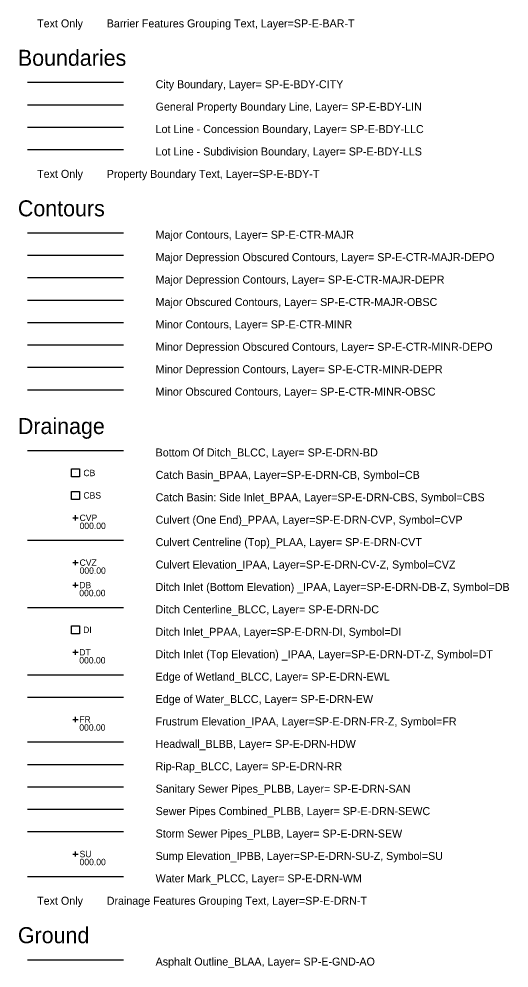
# Model space of a CAD drawing. Extents: x 500528 to 502626, y 4210261 to 4212624.
# Drawn here: x 500883.9 to 501036.9, y 4212030 to 4212326.4 of the extents above; entities that cross this region are included whole.
import ezdxf

# ---------------------------------------------------------------- set-up
doc = ezdxf.new("R2010")
doc.units = 0
for name, color, linetype in [('Default', 7, 'Continuous'), ('SP-E-BAR-T', 7, 'Continuous'), ('SP-E-BDY-CITY', 7, 'Continuous'), ('SP-E-BDY-LIN', 7, 'Continuous'), ('SP-E-BDY-LLC', 7, 'Continuous'), ('SP-E-BDY-LLS', 7, 'Continuous'), ('SP-E-BDY-T', 7, 'Continuous'), ('SP-E-CTR-MAJR', 7, 'Continuous'), ('SP-E-CTR-MAJR-DEPO', 7, 'Continuous'), ('SP-E-CTR-MAJR-DEPR', 7, 'Continuous'), ('SP-E-CTR-MAJR-OBSC', 7, 'Continuous'), ('SP-E-CTR-MINR', 7, 'Continuous'), ('SP-E-CTR-MINR-DEPO', 7, 'Continuous'), ('SP-E-CTR-MINR-DEPR', 7, 'Continuous'), ('SP-E-CTR-MINR-OBSC', 7, 'Continuous'), ('SP-E-DRN-BD', 7, 'Continuous'), ('SP-E-DRN-CB', 7, 'Continuous'), ('SP-E-DRN-CBS', 7, 'Continuous'), ('SP-E-DRN-CV-Z', 7, 'Continuous'), ('SP-E-DRN-CVP', 7, 'Continuous'), ('SP-E-DRN-CVT', 7, 'Continuous'), ('SP-E-DRN-DB-Z', 7, 'Continuous'), ('SP-E-DRN-DC', 7, 'Continuous'), ('SP-E-DRN-DI', 7, 'Continuous'), ('SP-E-DRN-DT-Z', 7, 'Continuous'), ('SP-E-DRN-EW', 7, 'Continuous'), ('SP-E-DRN-EWL', 7, 'Continuous'), ('SP-E-DRN-FR-Z', 7, 'Continuous'), ('SP-E-DRN-HDW', 7, 'Continuous'), ('SP-E-DRN-RR', 7, 'Continuous'), ('SP-E-DRN-SAN', 7, 'Continuous'), ('SP-E-DRN-SEW', 7, 'Continuous'), ('SP-E-DRN-SEWC', 7, 'Continuous'), ('SP-E-DRN-SU-Z', 7, 'Continuous'), ('SP-E-DRN-T', 7, 'Continuous'), ('SP-E-DRN-WM', 7, 'Continuous'), ('SP-E-GND-AO', 7, 'Continuous')]:
    doc.layers.add(name, color=color, linetype=linetype)

# ---------------------------------------------------------------- blocks, each defined once
blk = doc.blocks.new('POINT_DISPLAY')
at = {"layer": 'Default'}
blk.add_line((0, 0), (0, 0), dxfattribs=at)
blk = doc.blocks.new('CB')
at = {"layer": 'SP-E-DRN-T'}
blk.add_lwpolyline([(-0.125, 0.125), (0.125, 0.125), (0.125, -0.125), (-0.125, -0.125), (-0.125, 0.125)], dxfattribs=at)
at = {"layer": 'SP-E-DRN-CB'}
blk.add_blockref('POINT_DISPLAY', (0, 0), dxfattribs=at)
at = {"layer": 'SP-E-DRN-T'}
blk.add_text('CB', height=0.2, dxfattribs=at).set_placement((0.246, -0.1))
blk = doc.blocks.new('CBS')
at = {"layer": 'SP-E-DRN-T'}
blk.add_lwpolyline([(-0.125, 0.125), (0.125, 0.125), (0.125, -0.125), (-0.125, -0.125), (-0.125, 0.125)], dxfattribs=at)
at = {"layer": 'SP-E-DRN-CBS'}
blk.add_blockref('POINT_DISPLAY', (0, 0), dxfattribs=at)
at = {"layer": 'SP-E-DRN-T'}
blk.add_text('CBS', height=0.2, dxfattribs=at).set_placement((0.246, -0.1))
blk = doc.blocks.new('CVP')
at = {"layer": 'SP-E-DRN-CVP'}
for points in [[(-0.08, 0), (0.08, 0)], [(0, -0.08), (0, 0.08)]]:
    blk.add_lwpolyline(points, dxfattribs=at)
at = {"layer": 'SP-E-DRN-T'}
for s, p in [('CVP', (0.126, -0.1)), ('000.00', (0.126, -0.35))]:
    blk.add_text(s, height=0.2, dxfattribs=at).set_placement(p)
blk = doc.blocks.new('CVZ')
at = {"layer": 'SP-E-DRN-CV-Z'}
for points in [[(-0.08, 0), (0.08, 0)], [(0, -0.08), (0, 0.08)]]:
    blk.add_lwpolyline(points, dxfattribs=at)
at = {"layer": 'SP-E-DRN-T'}
for s, p in [('CVZ', (0.126, -0.1)), ('000.00', (0.126, -0.35))]:
    blk.add_text(s, height=0.2, dxfattribs=at).set_placement(p)
blk = doc.blocks.new('DB')
at = {"layer": 'SP-E-DRN-DB-Z'}
for points in [[(-0.08, 0), (0.08, 0)], [(0, -0.08), (0, 0.08)]]:
    blk.add_lwpolyline(points, dxfattribs=at)
at = {"layer": 'SP-E-DRN-T'}
for s, p in [('DB', (0.117, -0.1)), ('000.00', (0.117, -0.35))]:
    blk.add_text(s, height=0.2, dxfattribs=at).set_placement(p)
blk = doc.blocks.new('DI')
at = {"layer": 'SP-E-DRN-DI'}
for points in [[(-0.125, 0.125), (0.125, 0.125), (0.125, -0.125), (-0.125, -0.125), (-0.125, 0.125)], [(0, 0), (0, 0)]]:
    blk.add_lwpolyline(points, dxfattribs=at)
at = {"layer": 'SP-E-DRN-T'}
blk.add_text('DI', height=0.2, dxfattribs=at).set_placement((0.237, -0.1))
blk = doc.blocks.new('DT')
at = {"layer": 'SP-E-DRN-DT-Z'}
for points in [[(-0.08, 0), (0.08, 0)], [(0, -0.08), (0, 0.08)]]:
    blk.add_lwpolyline(points, dxfattribs=at)
at = {"layer": 'SP-E-DRN-T'}
for s, p in [('DT', (0.117, -0.1)), ('000.00', (0.117, -0.35))]:
    blk.add_text(s, height=0.2, dxfattribs=at).set_placement(p)
blk = doc.blocks.new('FR')
at = {"layer": 'SP-E-DRN-FR-Z'}
for points in [[(-0.08, 0), (0.08, 0)], [(0, -0.08), (0, 0.08)]]:
    blk.add_lwpolyline(points, dxfattribs=at)
at = {"layer": 'SP-E-DRN-T'}
for s, p in [('FR', (0.117, -0.1)), ('000.00', (0.117, -0.35))]:
    blk.add_text(s, height=0.2, dxfattribs=at).set_placement(p)
blk = doc.blocks.new('SU')
at = {"layer": 'SP-E-DRN-SU-Z'}
for points in [[(-0.08, 0), (0.08, 0)], [(0, -0.08), (0, 0.08)]]:
    blk.add_lwpolyline(points, dxfattribs=at)
at = {"layer": 'SP-E-DRN-T'}
for s, p in [('SU', (0.126, -0.1)), ('000.00', (0.126, -0.35))]:
    blk.add_text(s, height=0.2, dxfattribs=at).set_placement(p)

msp = doc.modelspace()

# ---------------------------------------------------------------- linework, layer by layer
at = {"layer": 'SP-E-BDY-CITY'}
msp.add_line((500886.55, 4212306.59), (500916.55, 4212306.59), dxfattribs=at)
at = {"layer": 'SP-E-BDY-LIN'}
msp.add_line((500886.55, 4212299.59), (500916.55, 4212299.59), dxfattribs=at)
at = {"layer": 'SP-E-BDY-LLC'}
msp.add_line((500886.55, 4212292.59), (500916.55, 4212292.59), dxfattribs=at)
at = {"layer": 'SP-E-BDY-LLS'}
msp.add_line((500886.55, 4212285.59), (500916.55, 4212285.59), dxfattribs=at)
at = {"layer": 'SP-E-CTR-MAJR'}
msp.add_line((500886.55, 4212259.59), (500916.55, 4212259.59), dxfattribs=at)
at = {"layer": 'SP-E-CTR-MAJR-DEPO'}
msp.add_line((500886.55, 4212252.59), (500916.55, 4212252.59), dxfattribs=at)
at = {"layer": 'SP-E-CTR-MAJR-DEPR'}
msp.add_line((500886.55, 4212245.59), (500916.55, 4212245.59), dxfattribs=at)
at = {"layer": 'SP-E-CTR-MAJR-OBSC'}
msp.add_line((500886.55, 4212238.59), (500916.55, 4212238.59), dxfattribs=at)
at = {"layer": 'SP-E-CTR-MINR'}
msp.add_line((500886.55, 4212231.59), (500916.55, 4212231.59), dxfattribs=at)
at = {"layer": 'SP-E-CTR-MINR-DEPO'}
msp.add_line((500886.55, 4212224.59), (500916.55, 4212224.59), dxfattribs=at)
at = {"layer": 'SP-E-CTR-MINR-DEPR'}
msp.add_line((500886.55, 4212217.59), (500916.55, 4212217.59), dxfattribs=at)
at = {"layer": 'SP-E-CTR-MINR-OBSC'}
msp.add_line((500886.55, 4212210.59), (500916.55, 4212210.59), dxfattribs=at)
at = {"layer": 'SP-E-DRN-BD'}
msp.add_line((500886.55, 4212191.59), (500916.55, 4212191.59), dxfattribs=at)
at = {"layer": 'SP-E-DRN-CVT'}
msp.add_line((500886.55, 4212163.59), (500916.55, 4212163.59), dxfattribs=at)
at = {"layer": 'SP-E-DRN-DC'}
msp.add_line((500886.55, 4212142.59), (500916.55, 4212142.59), dxfattribs=at)
at = {"layer": 'SP-E-DRN-EW'}
msp.add_line((500886.55, 4212114.59), (500916.55, 4212114.59), dxfattribs=at)
at = {"layer": 'SP-E-DRN-EWL'}
msp.add_line((500886.55, 4212121.59), (500916.55, 4212121.59), dxfattribs=at)
at = {"layer": 'SP-E-DRN-HDW'}
msp.add_line((500886.55, 4212100.59), (500916.55, 4212100.59), dxfattribs=at)
at = {"layer": 'SP-E-DRN-RR'}
msp.add_line((500886.55, 4212093.59), (500916.55, 4212093.59), dxfattribs=at)
at = {"layer": 'SP-E-DRN-SAN'}
msp.add_line((500886.55, 4212086.59), (500916.55, 4212086.59), dxfattribs=at)
at = {"layer": 'SP-E-DRN-SEW'}
msp.add_line((500886.55, 4212072.59), (500916.55, 4212072.59), dxfattribs=at)
at = {"layer": 'SP-E-DRN-SEWC'}
msp.add_line((500886.55, 4212079.59), (500916.55, 4212079.59), dxfattribs=at)
at = {"layer": 'SP-E-DRN-WM'}
msp.add_line((500886.55, 4212058.59), (500916.55, 4212058.59), dxfattribs=at)
at = {"layer": 'SP-E-GND-AO'}
msp.add_line((500886.55, 4212032.59), (500916.55, 4212032.59), dxfattribs=at)

# ---------------------------------------------------------------- block references
at = {"layer": 'SP-E-DRN-CB', "xscale": 10, "yscale": 10}
msp.add_blockref('CB', (500901.55, 4212184.59), dxfattribs=at)
at = {"layer": 'SP-E-DRN-CBS', "xscale": 10, "yscale": 10}
msp.add_blockref('CBS', (500901.55, 4212177.59), dxfattribs=at)
at = {"layer": 'SP-E-DRN-CV-Z', "xscale": 10, "yscale": 10}
msp.add_blockref('CVZ', (500901.55, 4212156.59), dxfattribs=at)
at = {"layer": 'SP-E-DRN-CVP', "xscale": 10, "yscale": 10}
msp.add_blockref('CVP', (500901.55, 4212170.59), dxfattribs=at)
at = {"layer": 'SP-E-DRN-DB-Z', "xscale": 10, "yscale": 10}
msp.add_blockref('DB', (500901.55, 4212149.59), dxfattribs=at)
at = {"layer": 'SP-E-DRN-DI', "xscale": 10, "yscale": 10}
msp.add_blockref('DI', (500901.55, 4212135.59), dxfattribs=at)
at = {"layer": 'SP-E-DRN-DT-Z', "xscale": 10, "yscale": 10}
msp.add_blockref('DT', (500901.55, 4212128.59), dxfattribs=at)
at = {"layer": 'SP-E-DRN-FR-Z', "xscale": 10, "yscale": 10}
msp.add_blockref('FR', (500901.55, 4212107.59), dxfattribs=at)
at = {"layer": 'SP-E-DRN-SU-Z', "xscale": 10, "yscale": 10}
msp.add_blockref('SU', (500901.55, 4212065.59), dxfattribs=at)

# ---------------------------------------------------------------- texts
at = {"layer": 'Default'}
for s, p in [('Boundaries ', (500883.55, 4212311.74)), ('Contours ', (500883.55, 4212264.74)), ('Drainage ', (500883.55, 4212196.74)), ('Ground ', (500883.55, 4212037.74))]:
    msp.add_text(s, height=5, dxfattribs=at).set_placement(p)
at = {"layer": 'SP-E-BAR-T'}
msp.add_text('Text Only        Barrier Features Grouping Text, Layer=SP-E-BAR-T', height=2.5, dxfattribs=at).set_placement((500889.55, 4212323.74))
at = {"layer": 'SP-E-BDY-CITY'}
msp.add_text('City Boundary, Layer= SP-E-BDY-CITY ', height=2.5, dxfattribs=at).set_placement((500926.55, 4212304.74))
at = {"layer": 'SP-E-BDY-LIN'}
msp.add_text('General Property Boundary Line, Layer= SP-E-BDY-LIN ', height=2.5, dxfattribs=at).set_placement((500926.55, 4212297.74))
at = {"layer": 'SP-E-BDY-LLC'}
msp.add_text('Lot Line - Concession Boundary, Layer= SP-E-BDY-LLC ', height=2.5, dxfattribs=at).set_placement((500926.55, 4212290.74))
at = {"layer": 'SP-E-BDY-LLS'}
msp.add_text('Lot Line - Subdivision Boundary, Layer= SP-E-BDY-LLS ', height=2.5, dxfattribs=at).set_placement((500926.55, 4212283.74))
at = {"layer": 'SP-E-BDY-T'}
msp.add_text('Text Only        Property Boundary Text, Layer=SP-E-BDY-T', height=2.5, dxfattribs=at).set_placement((500889.55, 4212276.74))
at = {"layer": 'SP-E-CTR-MAJR'}
msp.add_text('Major Contours, Layer= SP-E-CTR-MAJR ', height=2.5, dxfattribs=at).set_placement((500926.55, 4212257.74))
at = {"layer": 'SP-E-CTR-MAJR-DEPO'}
msp.add_text('Major Depression Obscured Contours, Layer= SP-E-CTR-MAJR-DEPO ', height=2.5, dxfattribs=at).set_placement((500926.55, 4212250.74))
at = {"layer": 'SP-E-CTR-MAJR-DEPR'}
msp.add_text('Major Depression Contours, Layer= SP-E-CTR-MAJR-DEPR ', height=2.5, dxfattribs=at).set_placement((500926.55, 4212243.74))
at = {"layer": 'SP-E-CTR-MAJR-OBSC'}
msp.add_text('Major Obscured Contours, Layer= SP-E-CTR-MAJR-OBSC ', height=2.5, dxfattribs=at).set_placement((500926.55, 4212236.74))
at = {"layer": 'SP-E-CTR-MINR'}
msp.add_text('Minor Contours, Layer= SP-E-CTR-MINR ', height=2.5, dxfattribs=at).set_placement((500926.55, 4212229.74))
at = {"layer": 'SP-E-CTR-MINR-DEPO'}
msp.add_text('Minor Depression Obscured Contours, Layer= SP-E-CTR-MINR-DEPO ', height=2.5, dxfattribs=at).set_placement((500926.55, 4212222.74))
at = {"layer": 'SP-E-CTR-MINR-DEPR'}
msp.add_text('Minor Depression Contours, Layer= SP-E-CTR-MINR-DEPR ', height=2.5, dxfattribs=at).set_placement((500926.55, 4212215.74))
at = {"layer": 'SP-E-CTR-MINR-OBSC'}
msp.add_text('Minor Obscured Contours, Layer= SP-E-CTR-MINR-OBSC ', height=2.5, dxfattribs=at).set_placement((500926.55, 4212208.74))
at = {"layer": 'SP-E-DRN-BD'}
msp.add_text('Bottom Of Ditch_BLCC, Layer= SP-E-DRN-BD ', height=2.5, dxfattribs=at).set_placement((500926.55, 4212189.74))
at = {"layer": 'SP-E-DRN-CB'}
msp.add_text('Catch Basin_BPAA, Layer=SP-E-DRN-CB, Symbol=CB ', height=2.5, dxfattribs=at).set_placement((500926.55, 4212182.74))
at = {"layer": 'SP-E-DRN-CBS'}
msp.add_text('Catch Basin: Side Inlet_BPAA, Layer=SP-E-DRN-CBS, Symbol=CBS ', height=2.5, dxfattribs=at).set_placement((500926.55, 4212175.74))
at = {"layer": 'SP-E-DRN-CV-Z'}
msp.add_text('Culvert Elevation_IPAA, Layer=SP-E-DRN-CV-Z, Symbol=CVZ ', height=2.5, dxfattribs=at).set_placement((500926.55, 4212154.74))
at = {"layer": 'SP-E-DRN-CVP'}
msp.add_text('Culvert (One End)_PPAA, Layer=SP-E-DRN-CVP, Symbol=CVP ', height=2.5, dxfattribs=at).set_placement((500926.55, 4212168.74))
at = {"layer": 'SP-E-DRN-CVT'}
msp.add_text('Culvert Centreline (Top)_PLAA, Layer= SP-E-DRN-CVT ', height=2.5, dxfattribs=at).set_placement((500926.55, 4212161.74))
at = {"layer": 'SP-E-DRN-DB-Z'}
msp.add_text('Ditch Inlet (Bottom Elevation) _IPAA, Layer=SP-E-DRN-DB-Z, Symbol=DB ', height=2.5, dxfattribs=at).set_placement((500926.55, 4212147.74))
at = {"layer": 'SP-E-DRN-DC'}
msp.add_text('Ditch Centerline_BLCC, Layer= SP-E-DRN-DC ', height=2.5, dxfattribs=at).set_placement((500926.55, 4212140.74))
at = {"layer": 'SP-E-DRN-DI'}
msp.add_text('Ditch Inlet_PPAA, Layer=SP-E-DRN-DI, Symbol=DI ', height=2.5, dxfattribs=at).set_placement((500926.55, 4212133.74))
at = {"layer": 'SP-E-DRN-DT-Z'}
msp.add_text('Ditch Inlet (Top Elevation) _IPAA, Layer=SP-E-DRN-DT-Z, Symbol=DT ', height=2.5, dxfattribs=at).set_placement((500926.55, 4212126.74))
at = {"layer": 'SP-E-DRN-EW'}
msp.add_text('Edge of Water_BLCC, Layer= SP-E-DRN-EW ', height=2.5, dxfattribs=at).set_placement((500926.55, 4212112.74))
at = {"layer": 'SP-E-DRN-EWL'}
msp.add_text('Edge of Wetland_BLCC, Layer= SP-E-DRN-EWL ', height=2.5, dxfattribs=at).set_placement((500926.55, 4212119.74))
at = {"layer": 'SP-E-DRN-FR-Z'}
msp.add_text('Frustrum Elevation_IPAA, Layer=SP-E-DRN-FR-Z, Symbol=FR ', height=2.5, dxfattribs=at).set_placement((500926.55, 4212105.74))
at = {"layer": 'SP-E-DRN-HDW'}
msp.add_text('Headwall_BLBB, Layer= SP-E-DRN-HDW ', height=2.5, dxfattribs=at).set_placement((500926.55, 4212098.74))
at = {"layer": 'SP-E-DRN-RR'}
msp.add_text('Rip-Rap_BLCC, Layer= SP-E-DRN-RR ', height=2.5, dxfattribs=at).set_placement((500926.55, 4212091.74))
at = {"layer": 'SP-E-DRN-SAN'}
msp.add_text('Sanitary Sewer Pipes_PLBB, Layer= SP-E-DRN-SAN ', height=2.5, dxfattribs=at).set_placement((500926.55, 4212084.74))
at = {"layer": 'SP-E-DRN-SEW'}
msp.add_text('Storm Sewer Pipes_PLBB, Layer= SP-E-DRN-SEW ', height=2.5, dxfattribs=at).set_placement((500926.55, 4212070.74))
at = {"layer": 'SP-E-DRN-SEWC'}
msp.add_text('Sewer Pipes Combined_PLBB, Layer= SP-E-DRN-SEWC ', height=2.5, dxfattribs=at).set_placement((500926.55, 4212077.74))
at = {"layer": 'SP-E-DRN-SU-Z'}
msp.add_text('Sump Elevation_IPBB, Layer=SP-E-DRN-SU-Z, Symbol=SU ', height=2.5, dxfattribs=at).set_placement((500926.55, 4212063.74))
at = {"layer": 'SP-E-DRN-T'}
msp.add_text('Text Only        Drainage Features Grouping Text, Layer=SP-E-DRN-T', height=2.5, dxfattribs=at).set_placement((500889.55, 4212049.74))
at = {"layer": 'SP-E-DRN-WM'}
msp.add_text('Water Mark_PLCC, Layer= SP-E-DRN-WM ', height=2.5, dxfattribs=at).set_placement((500926.55, 4212056.74))
at = {"layer": 'SP-E-GND-AO'}
msp.add_text('Asphalt Outline_BLAA, Layer= SP-E-GND-AO ', height=2.5, dxfattribs=at).set_placement((500926.55, 4212030.74))

doc.saveas('drawing.dxf')
